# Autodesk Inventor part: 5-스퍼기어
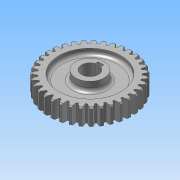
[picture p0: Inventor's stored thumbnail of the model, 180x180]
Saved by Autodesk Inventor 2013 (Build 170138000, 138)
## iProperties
Created: 2013-08
Part Number: 5-스퍼기어
Material: 강
Document SubType Name: Modeling
Designer: 한국산업디자인학원
Categories: <?xml version="1.0" encoding="UTF-16"?> <MemberInstance><Categories><FamilyTemplate><FamilyTemplateParameter ValueType="xs:double" Id="1" ObjectReferenceKey="da
Density: 1 g/cm^3
CustomPartVersion: 1
Author: 한국산업디자인학원
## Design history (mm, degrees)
sketch "Sketch1"
  geometry: C1 r 37 at (0, 0)
  constraints: 1 centre point
  dimensions: "d0" = 74 diameter of C1 (= da_da)
extrude "Extrusion1" new body sketch "Sketch1" distance "d1" = 15 (= da_b); taper "d2" = 0 deg
chamfer "모따기1" distance "d49" = 1; stored, may be unused: second distance "d50" = 2, angle "d51" = 45 deg
sketch "스케치3"
  geometry: L1 (36, 0)-(-36, 0) reference; L2 (-36, 15)-(36, 15) reference; L3 (-27.5, 0)-(-12.5, 0); L4 (-12.5, 0)-(-12.5, 5); L5 (-12.5, 5)-(-27.5, 5); L6 (-27.5, 5)-(-27.5, 0); L7 (-12.5, 15)-(-27.5, 15); L8 (-27.5, 15)-(-27.5, 10); L9 (-27.5, 10)-(-12.5, 10); L10 (-12.5, 10)-(-12.5, 15); L11 (0, 0)-(0, 15)
  constraints: 18 end point, 4 parallel, 2 collinear, 2 horizontal, 2 perpendicular, 2 point on line, 1 midpoint
  dimensions: "d52" = 5 distance of L9.end L7.start; "d54" = 5 distance of L3.end L4.end; "d55" = 55 diameter of L6 L11; "d56" = 25 diameter of L4 L11
revolve "회전1" sketch "스케치3" stored, may be unused: angle "d57" = 90 deg
workplane "Work Plane2"
feature "피치 지름" dims "d4" = 10, "d5" = 0
workplane "Work Plane8"
workplane "Work Plane9"
feature "스퍼 기어" dims "da_b" = 15, "da_d" = 70, "da_aw" = 70, "da_da" = 74, "da_df" = 65, "da_dw" = 70, angle "da_beta" = 0 deg, "da_lefttooth" = 0, "da_righttooth" = 0
node "작업 평면11"
sketch "스케치4"
  geometry: C1 r 12.5 at (0, 0) reference; 1 further point
extrude "돌출2" join sketch "스케치4" distance "d59" = 31; taper "d60" = 0 deg
sketch "스케치5"
  geometry: L1 (-2.5, 7.071)-(-2.5, 9.8); L2 (-2.5, 9.8)-(2.5, 9.8); L3 (2.5, 9.8)-(2.5, 7.071); C1 r 12.5 at (0, 0) reference; A1 r 7.5 centre (0, 0) between (-2.5, 7.071) and (2.5, 7.071)
  constraints: 6 end point, 2 parallel, 2 point on circle, 1 centre point, 1 coincident, 1 perpendicular, 1 vertical
  dimensions: "d61" = 15 diameter of A1; "d63" = 5 distance of L1.end L2.end; "d64" = 17.3 dimension on A1 L2
extrude "돌출3" cut sketch "스케치5" stored distance "d65" = 31; taper "d66" = 0 deg
fillet "모깎기1" dims "d67" = 3
body "Solid1"
sketch "Sketch2"
  geometry: C1 r 37 at (0, 0) reference; C2 r 35 at (0, 0)
  constraints: 1 centre point, 1 coincident
  dimensions: "d3" = 70 diameter of C2 (= da_dw)
body "Srf1"
other parameters: "d17" = 0, "d34" = 0.8976 (computed from da_z), "d39" = 0, "d41" = 0, "d47" = 0, "d48" = 0, "d58" = 3
